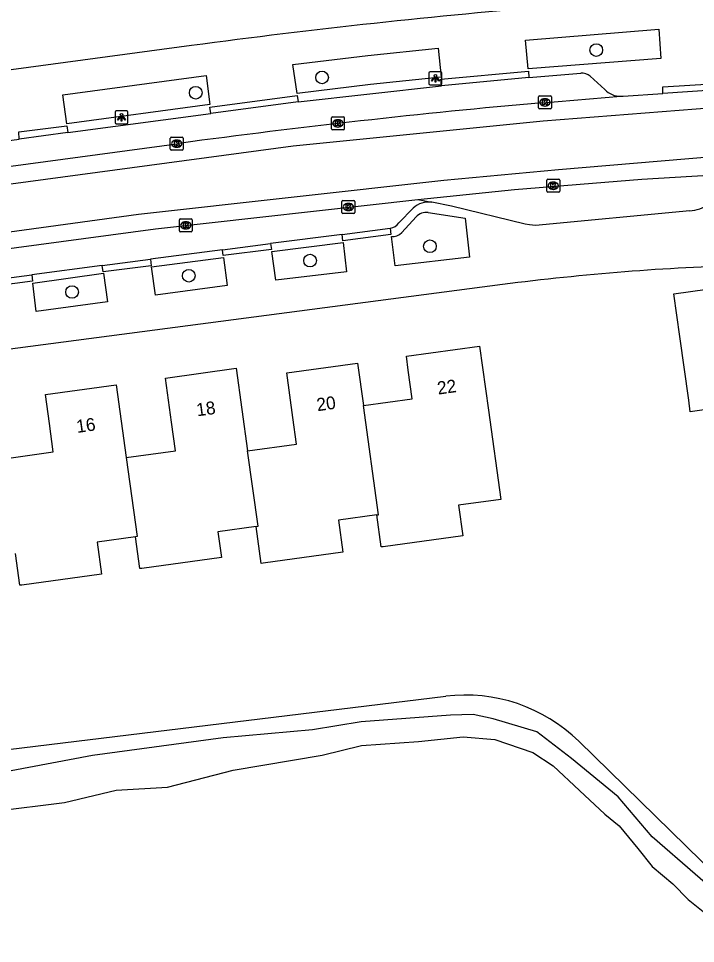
# Model space of a CAD drawing. Extents: x 163427 to 164190, y 380331 to 381641.
# Drawn here: x 163553.6 to 163606.1, y 380852.1 to 380923.8 of the extents above; entities that cross this region are included whole.
import ezdxf

# ---------------------------------------------------------------- set-up
doc = ezdxf.new("R2010")
doc.units = 0
for name, color, linetype in [('IMGEO_Boom', 7, 'Continuous'), ('IMGEO_Fietspad_gesloten', 7, 'Continuous'), ('IMGEO_Gemengd_bos', 7, 'Continuous'), ('IMGEO_Hek', 7, 'Continuous'), ('IMGEO_Kolk', 7, 'Continuous'), ('IMGEO_Lichtpunt', 7, 'Continuous'), ('IMGEO_Pand', 7, 'Continuous'), ('IMGEO_Pand_nummerreeks', 7, 'Continuous'), ('IMGEO_Rijbaan_lokaal_gesloten', 7, 'Continuous'), ('IMGEO_Rijbaan_lokaal_open', 7, 'Continuous'), ('IMGEO_Voetpad_open', 7, 'Continuous'), ('IMGEO_Waterloop', 7, 'Continuous')]:
    doc.layers.add(name, color=color, linetype=linetype)

msp = doc.modelspace()

# ---------------------------------------------------------------- linework, layer by layer
at = {"layer": 'IMGEO_Boom'}
for centre in [(163598.403, 380921.383), (163577.143, 380919.26), (163567.348, 380918.08), (163585.502, 380906.177), (163576.207, 380905.06), (163566.806, 380903.885), (163557.758, 380902.627)]:
    msp.add_circle(centre, 0.489, dxfattribs=at)
at = {"layer": 'IMGEO_Fietspad_gesloten'}
msp.add_lwpolyline([(163546.112, 380905.102), (163564.218, 380907.521), (163584.562, 380909.802)], dxfattribs=at)
at = {"layer": 'IMGEO_Gemengd_bos'}
for points in [[(163493.384, 380859.911), (163586.726, 380871.286)], [(163597.048, 380867.792), (163612.499, 380852.69), (163645.162, 380821.2)]]:
    msp.add_lwpolyline(points, dxfattribs=at)
msp.add_arc((163588.249, 380858.793), 12.586, 45.64563, 96.95242, dxfattribs=at)
at = {"layer": 'IMGEO_Hek'}
msp.add_lwpolyline([(163645.162, 380821.2), (163612.499, 380852.69), (163597.048, 380867.792)], dxfattribs=at)
at = {"layer": 'IMGEO_Kolk'}
for p, q in [((163593.922, 380916.901), (163593.922, 380917.753)), ((163593.997, 380917.827), (163594.849, 380917.827)), ((163594.41, 380917.607), (163594.435, 380917.607)), ((163594.923, 380917.753), (163594.923, 380916.901)), ((163594.433, 380917.047), (163594.408, 380917.047)), ((163577.941, 380916.199), (163578.793, 380916.199)), ((163594.849, 380916.827), (163593.997, 380916.827)), ((163577.866, 380915.273), (163577.866, 380916.125)), ((163578.354, 380915.979), (163578.379, 380915.979)), ((163578.867, 380916.125), (163578.867, 380915.273)), ((163578.793, 380915.199), (163577.941, 380915.199)), ((163578.377, 380915.419), (163578.352, 380915.419)), ((163565.374, 380913.706), (163565.374, 380914.558)), ((163565.449, 380914.632), (163566.301, 380914.632)), ((163565.862, 380914.412), (163565.887, 380914.412)), ((163566.375, 380914.558), (163566.375, 380913.706)), ((163566.301, 380913.632), (163565.449, 380913.632)), ((163565.885, 380913.852), (163565.86, 380913.852)), ((163594.569, 380910.437), (163594.569, 380911.289)), ((163594.644, 380911.363), (163595.496, 380911.363)), ((163595.057, 380911.143), (163595.082, 380911.143)), ((163595.57, 380911.289), (163595.57, 380910.437)), ((163595.08, 380910.583), (163595.055, 380910.583)), ((163578.755, 380909.717), (163579.607, 380909.717)), ((163595.496, 380910.363), (163594.644, 380910.363)), ((163578.68, 380908.791), (163578.68, 380909.643)), ((163579.168, 380909.497), (163579.193, 380909.497)), ((163579.681, 380909.643), (163579.681, 380908.791)), ((163566.15, 380908.298), (163567.002, 380908.298)), ((163579.607, 380908.717), (163578.755, 380908.717)), ((163579.191, 380908.937), (163579.166, 380908.937)), ((163566.075, 380907.372), (163566.075, 380908.224)), ((163566.563, 380908.078), (163566.588, 380908.078)), ((163567.076, 380908.224), (163567.076, 380907.372)), ((163567.002, 380907.298), (163566.15, 380907.298)), ((163566.586, 380907.518), (163566.561, 380907.518))]:
    msp.add_line(p, q, dxfattribs=at)
for points in [[(163593.922, 380916.901), (163593.922, 380917.753)], [(163593.997, 380917.827), (163594.849, 380917.827)], [(163594.923, 380917.753), (163594.923, 380916.901)], [(163594.243, 380917.527), (163594.366, 380917.527), (163594.366, 380917.376), (163594.496, 380917.527), (163594.66, 380917.527), (163594.514, 380917.376), (163594.667, 380917.127), (163594.515, 380917.127), (163594.43, 380917.291), (163594.366, 380917.224), (163594.366, 380917.127), (163594.243, 380917.127), (163594.243, 380917.527)], [(163577.941, 380916.199), (163578.793, 380916.199)], [(163594.849, 380916.827), (163593.997, 380916.827)], [(163577.866, 380915.273), (163577.866, 380916.125)], [(163578.187, 380915.899), (163578.31, 380915.899), (163578.31, 380915.748), (163578.44, 380915.899), (163578.604, 380915.899), (163578.458, 380915.748), (163578.611, 380915.499), (163578.459, 380915.499), (163578.374, 380915.663), (163578.31, 380915.596), (163578.31, 380915.499), (163578.187, 380915.499), (163578.187, 380915.899)], [(163578.867, 380916.125), (163578.867, 380915.273)], [(163578.793, 380915.199), (163577.941, 380915.199)], [(163565.374, 380913.706), (163565.374, 380914.558)], [(163565.449, 380914.632), (163566.301, 380914.632)], [(163565.695, 380914.332), (163565.818, 380914.332), (163565.818, 380914.181), (163565.948, 380914.332), (163566.112, 380914.332), (163565.966, 380914.181), (163566.119, 380913.932), (163565.967, 380913.932), (163565.882, 380914.096), (163565.818, 380914.029), (163565.818, 380913.932), (163565.695, 380913.932), (163565.695, 380914.332)], [(163566.375, 380914.558), (163566.375, 380913.706)], [(163566.301, 380913.632), (163565.449, 380913.632)], [(163594.569, 380910.437), (163594.569, 380911.289)], [(163594.644, 380911.363), (163595.496, 380911.363)], [(163595.57, 380911.289), (163595.57, 380910.437)], [(163594.89, 380911.063), (163595.013, 380911.063), (163595.013, 380910.912), (163595.143, 380911.063), (163595.307, 380911.063), (163595.161, 380910.912), (163595.314, 380910.663), (163595.162, 380910.663), (163595.077, 380910.827), (163595.013, 380910.76), (163595.013, 380910.663), (163594.89, 380910.663), (163594.89, 380911.063)], [(163578.755, 380909.717), (163579.607, 380909.717)], [(163595.496, 380910.363), (163594.644, 380910.363)], [(163578.68, 380908.791), (163578.68, 380909.643)], [(163579.001, 380909.417), (163579.124, 380909.417), (163579.124, 380909.266), (163579.254, 380909.417), (163579.418, 380909.417), (163579.272, 380909.266), (163579.425, 380909.017), (163579.273, 380909.017), (163579.188, 380909.181), (163579.124, 380909.114), (163579.124, 380909.017), (163579.001, 380909.017), (163579.001, 380909.417)], [(163579.681, 380909.643), (163579.681, 380908.791)], [(163566.15, 380908.298), (163567.002, 380908.298)], [(163579.607, 380908.717), (163578.755, 380908.717)], [(163566.075, 380907.372), (163566.075, 380908.224)], [(163566.396, 380907.998), (163566.519, 380907.998), (163566.519, 380907.847), (163566.649, 380907.998), (163566.813, 380907.998), (163566.667, 380907.847), (163566.82, 380907.598), (163566.668, 380907.598), (163566.583, 380907.762), (163566.519, 380907.695), (163566.519, 380907.598), (163566.396, 380907.598), (163566.396, 380907.998)], [(163567.076, 380908.224), (163567.076, 380907.372)], [(163567.002, 380907.298), (163566.15, 380907.298)]]:
    msp.add_lwpolyline(points, dxfattribs=at)
for centre, start, end in [((163593.999, 380917.751), 91.55205, 178.44795), ((163593.999, 380917.751), 91.55205, 178.44795), ((163594.847, 380917.751), 1.55205, 88.44795), ((163594.847, 380917.751), 1.55205, 88.44795), ((163593.999, 380916.903), 181.55205, 268.44795), ((163593.999, 380916.903), 181.55205, 268.44795), ((163594.847, 380916.903), 271.55205, 358.44795), ((163594.847, 380916.903), 271.55205, 358.44795), ((163577.943, 380916.123), 91.55205, 178.44795), ((163577.943, 380916.123), 91.55205, 178.44795), ((163578.791, 380916.123), 1.55205, 88.44795), ((163578.791, 380916.123), 1.55205, 88.44795), ((163577.943, 380915.275), 181.55205, 268.44795), ((163577.943, 380915.275), 181.55205, 268.44795), ((163578.791, 380915.275), 271.55205, 358.44795), ((163578.791, 380915.275), 271.55205, 358.44795), ((163565.451, 380914.556), 91.55205, 178.44795), ((163565.451, 380914.556), 91.55205, 178.44795), ((163566.299, 380914.556), 1.55205, 88.44795), ((163566.299, 380914.556), 1.55205, 88.44795), ((163565.451, 380913.708), 181.55205, 268.44795), ((163565.451, 380913.708), 181.55205, 268.44795), ((163566.299, 380913.708), 271.55205, 358.44795), ((163566.299, 380913.708), 271.55205, 358.44795), ((163594.646, 380911.287), 91.55205, 178.44795), ((163594.646, 380911.287), 91.55205, 178.44795), ((163595.494, 380911.287), 1.55205, 88.44795), ((163595.494, 380911.287), 1.55205, 88.44795), ((163594.646, 380910.439), 181.55205, 268.44795), ((163594.646, 380910.439), 181.55205, 268.44795), ((163595.494, 380910.439), 271.55205, 358.44795), ((163595.494, 380910.439), 271.55205, 358.44795), ((163578.757, 380909.641), 91.55205, 178.44795), ((163578.757, 380909.641), 91.55205, 178.44795), ((163579.605, 380909.641), 1.55205, 88.44795), ((163579.605, 380909.641), 1.55205, 88.44795), ((163566.152, 380908.222), 91.55205, 178.44795), ((163566.152, 380908.222), 91.55205, 178.44795), ((163567, 380908.222), 1.55205, 88.44795), ((163567, 380908.222), 1.55205, 88.44795), ((163578.757, 380908.793), 181.55205, 268.44795), ((163578.757, 380908.793), 181.55205, 268.44795), ((163579.605, 380908.793), 271.55205, 358.44795), ((163579.605, 380908.793), 271.55205, 358.44795), ((163566.152, 380907.374), 181.55205, 268.44795), ((163566.152, 380907.374), 181.55205, 268.44795), ((163567, 380907.374), 271.55205, 358.44795), ((163567, 380907.374), 271.55205, 358.44795)]:
    msp.add_arc(centre, 0.0765, start, end, dxfattribs=at)
for centre, major_axis, ratio, start_param, end_param in [((163594.409, 380917.327), (-0.387, 0.002), 0.722429, 4.712389, 7.853982), ((163594.434, 380917.327), (-0.39, 0.002), 0.717154, 1.570796, 4.712389), ((163578.353, 380915.699), (-0.387, 0.002), 0.722429, 4.712389, 7.853982), ((163578.378, 380915.699), (-0.39, 0.002), 0.717154, 1.570796, 4.712389), ((163565.861, 380914.132), (-0.387, 0.002), 0.722429, 4.712389, 7.853982), ((163565.886, 380914.132), (-0.39, 0.002), 0.717154, 1.570796, 4.712389), ((163595.056, 380910.863), (-0.387, 0.002), 0.722429, 4.712389, 7.853982), ((163595.081, 380910.863), (-0.39, 0.002), 0.717154, 1.570796, 4.712389), ((163579.167, 380909.217), (-0.387, 0.002), 0.722429, 4.712389, 7.853982), ((163579.192, 380909.217), (-0.39, 0.002), 0.717154, 1.570796, 4.712389), ((163566.562, 380907.798), (-0.387, 0.002), 0.722429, 4.712389, 7.853982), ((163566.587, 380907.798), (-0.39, 0.002), 0.717154, 1.570796, 4.712389)]:
    msp.add_ellipse(centre, major_axis=major_axis, ratio=ratio, start_param=start_param, end_param=end_param, dxfattribs=at)
at = {"layer": 'IMGEO_Lichtpunt'}
for p, q in [((163585.431, 380919.593), (163585.431, 380918.786)), ((163585.431, 380919.593), (163585.431, 380918.786)), ((163586.333, 380919.688), (163585.525, 380919.688)), ((163586.333, 380919.688), (163585.525, 380919.688)), ((163586.427, 380918.786), (163586.427, 380919.593)), ((163586.427, 380918.786), (163586.427, 380919.593)), ((163585.525, 380918.692), (163586.333, 380918.692)), ((163585.525, 380918.692), (163586.333, 380918.692)), ((163561.088, 380916.573), (163561.088, 380915.766)), ((163561.088, 380916.573), (163561.088, 380915.766)), ((163561.99, 380916.668), (163561.182, 380916.668)), ((163561.99, 380916.668), (163561.182, 380916.668)), ((163562.084, 380915.766), (163562.084, 380916.573)), ((163562.084, 380915.766), (163562.084, 380916.573)), ((163561.182, 380915.672), (163561.99, 380915.672)), ((163561.182, 380915.672), (163561.99, 380915.672))]:
    msp.add_line(p, q, dxfattribs=at)
for points in [[(163585.805, 380919.257), (163585.844, 380919.229), (163585.656, 380918.967), (163585.618, 380918.994), (163585.805, 380919.257)], [(163585.907, 380919.209), (163585.954, 380919.209), (163585.954, 380918.887), (163585.907, 380918.887), (163585.907, 380919.209)], [(163586.017, 380919.229), (163586.055, 380919.256), (163586.242, 380918.994), (163586.203, 380918.966), (163586.017, 380919.229)], [(163561.462, 380916.237), (163561.501, 380916.209), (163561.313, 380915.947), (163561.275, 380915.974), (163561.462, 380916.237)], [(163561.564, 380916.189), (163561.611, 380916.189), (163561.611, 380915.867), (163561.564, 380915.867), (163561.564, 380916.189)], [(163561.674, 380916.209), (163561.712, 380916.236), (163561.899, 380915.974), (163561.86, 380915.946), (163561.674, 380916.209)]]:
    msp.add_lwpolyline(points, dxfattribs=at)
for centre in [(163585.93, 380919.391), (163561.587, 380916.371)]:
    msp.add_circle(centre, 0.0994, dxfattribs=at)
for centre, start, end in [((163585.525, 380919.593), 90, 180), ((163585.525, 380919.593), 90, 180), ((163586.333, 380919.593), 0, 90), ((163586.333, 380919.593), 0, 90), ((163585.525, 380918.786), 180, 270), ((163585.525, 380918.786), 180, 270), ((163586.333, 380918.786), 270, 0), ((163586.333, 380918.786), 270, 360), ((163561.182, 380916.573), 90, 180), ((163561.182, 380916.573), 90, 180), ((163561.99, 380916.573), 0, 90), ((163561.99, 380916.573), 0, 90), ((163561.182, 380915.766), 180, 270), ((163561.182, 380915.766), 180, 270), ((163561.99, 380915.766), 270, 0), ((163561.99, 380915.766), 270, 360)]:
    msp.add_arc(centre, 0.0946, start, end, dxfattribs=at)
at = {"layer": 'IMGEO_Pand'}
for points in [[(163609.011, 380884.11), (163607.679, 380893.619), (163605.698, 380893.341), (163605.573, 380894.234), (163604.88, 380899.185), (163604.416, 380902.498), (163612.354, 380903.601), (163612.81, 380900.292), (163613.286, 380896.835), (163616.257, 380897.248), (163617.925, 380885.358), (163612.974, 380884.665), (163609.011, 380884.11)], [(163580.354, 380893.822), (163584.135, 380894.343), (163583.829, 380896.562), (163583.68, 380897.642), (163589.343, 380898.423), (163590.036, 380893.472), (163591.006, 380886.545), (163587.731, 380886.094), (163588.056, 380883.729), (163581.873, 380882.879), (163581.724, 380882.858), (163581.382, 380885.341)], [(163571.367, 380890.303), (163575.165, 380890.826), (163574.88, 380892.897), (163574.403, 380896.364), (163579.896, 380897.121), (163580.354, 380893.822)], [(163561.962, 380889.797), (163565.776, 380890.324), (163565.471, 380892.532), (163564.998, 380895.956), (163570.479, 380896.712), (163571.367, 380890.303)], [(163552.496, 380889.7), (163556.301, 380890.225), (163555.997, 380892.424), (163555.687, 380894.67), (163561.178, 380895.428), (163561.962, 380889.797)], [(163581.382, 380885.341), (163581.528, 380885.361), (163580.354, 380893.822)], [(163561.962, 380889.797), (163562.815, 380883.673), (163562.67, 380883.653)], [(163572.028, 380884.447), (163572.175, 380884.467), (163571.367, 380890.303)], [(163581.382, 380885.341), (163578.413, 380884.933), (163578.755, 380882.449), (163572.572, 380881.598), (163572.423, 380881.577), (163572.028, 380884.447)], [(163572.028, 380884.447), (163569.059, 380884.038), (163569.333, 380882.049), (163563.159, 380881.2), (163563.01, 380881.179), (163562.67, 380883.653)], [(163562.67, 380883.653), (163559.701, 380883.244), (163560.043, 380880.76), (163553.85, 380879.908), (163553.701, 380879.887), (163553.362, 380882.351)]]:
    msp.add_lwpolyline(points, dxfattribs=at)
at = {"layer": 'IMGEO_Rijbaan_lokaal_gesloten'}
for points in [[(163607.38, 380918.278), (163607.459, 380916.901), (163594.29, 380915.88), (163574.895, 380913.939), (163529.367, 380907.811), (163518.508, 380906.15), (163518.238, 380907.701)], [(163594.236, 380917.3), (163600.308, 380917.8)], [(163600.308, 380917.8), (163600.49, 380917.815), (163603.576, 380918.027)], [(163607.38, 380918.278), (163603.576, 380918.027)], [(163682.084, 380914.454), (163682.039, 380914.453), (163667.849, 380914.247), (163641.715, 380914.042), (163613.539, 380913.634), (163595.47, 380912.102), (163586.588, 380911.285), (163562.905, 380908.63), (163550.246, 380906.894), (163542.996, 380905.847), (163538.913, 380905.03), (163527.53, 380902.17), (163513.545, 380898.902), (163493.877, 380894.347)], [(163518.238, 380907.701), (163566.057, 380914.153)]]:
    msp.add_lwpolyline(points, dxfattribs=at)
msp.add_arc((163647.924, 380308.83), 610.834, 95.042405, 97.702246, dxfattribs=at)
at = {"layer": 'IMGEO_Rijbaan_lokaal_open'}
for points in [[(163593.185, 380919.252), (163586.408, 380918.617)], [(163593.185, 380919.252), (163597.205, 380919.598)], [(163597.924, 380919.35), (163599.078, 380918.328)], [(163575.285, 380917.378), (163586.408, 380918.617)], [(163575.285, 380917.378), (163568.512, 380916.471)], [(163557.432, 380914.987), (163568.512, 380916.471)], [(163557.432, 380914.987), (163553.66, 380914.482)], [(163521.671, 380910.197), (163553.66, 380914.482)], [(163584.562, 380909.802), (163592.055, 380910.574), (163601.938, 380911.38), (163611.837, 380911.964)], [(163584.562, 380909.802), (163585.658, 380909.583)], [(163605.654, 380908.909), (163593.683, 380907.793), (163593.225, 380907.828), (163592.888, 380907.877), (163587.172, 380909.281), (163585.658, 380909.583)]]:
    msp.add_lwpolyline(points, dxfattribs=at)
for centre, radius, start, end in [((163597.259, 380918.587), 1.012, 48.89889, 93.04008), ((163600.269, 380919.406), 1.607, 222.15316, 271.38221), ((163604.989, 380913.587), 4.725, 278.08572, 297.23979)]:
    msp.add_arc(centre, radius, start, end, dxfattribs=at)
at = {"layer": 'IMGEO_Voetpad_open'}
for points in [[(163592.914, 380922.155), (163603.244, 380923.005), (163603.418, 380920.741), (163593.119, 380919.928), (163592.914, 380922.155)], [(163567.021, 380921.728), (163552.058, 380919.715)], [(163580.908, 380918.708), (163575.202, 380918.02), (163574.873, 380920.263), (163580.701, 380920.965), (163586.145, 380921.539), (163586.369, 380919.291), (163580.908, 380918.708)], [(163586.408, 380918.617), (163586.361, 380919.121), (163593.139, 380919.749), (163593.185, 380919.252)], [(163568.45, 380917.161), (163557.361, 380915.675), (163557.034, 380917.924), (163568.153, 380919.422), (163568.45, 380917.161)], [(163603.576, 380918.027), (163603.576, 380918.542), (163607.345, 380918.78), (163607.38, 380918.278)], [(163568.512, 380916.471), (163568.446, 380916.966), (163575.219, 380917.873), (163575.285, 380917.378)], [(163553.66, 380914.482), (163553.616, 380915.034), (163557.361, 380915.523), (163557.432, 380914.987)], [(163584.193, 380909.131), (163583.103, 380907.978)], [(163585.357, 380908.782), (163588.24, 380908.352), (163588.583, 380905.341), (163582.816, 380904.651)], [(163583.32, 380907.233), (163584.437, 380908.45)], [(163582.425, 380907.582), (163582.474, 380907.078), (163578.756, 380906.604), (163578.687, 380907.096)], [(163578.687, 380907.096), (163582.425, 380907.582)], [(163578.687, 380907.096), (163573.153, 380906.376)], [(163582.816, 380904.651), (163582.517, 380906.924)], [(163573.153, 380906.376), (163573.222, 380905.916), (163569.48, 380905.45), (163569.42, 380905.89)], [(163569.42, 380905.89), (163573.153, 380906.376)], [(163573.544, 380903.543), (163573.243, 380905.769), (163578.776, 380906.459), (163579.043, 380904.199), (163573.544, 380903.543)], [(163569.42, 380905.89), (163563.836, 380905.164)], [(163560.097, 380904.678), (163554.627, 380903.966)], [(163563.836, 380905.164), (163563.9, 380904.669), (163560.161, 380904.183), (163560.097, 380904.678)], [(163560.097, 380904.678), (163563.836, 380905.164)], [(163564.212, 380902.374), (163563.913, 380904.583), (163569.49, 380905.3), (163569.794, 380903.122), (163564.212, 380902.374)], [(163554.627, 380903.966), (163554.691, 380903.471), (163550.936, 380902.983), (163550.872, 380903.478)], [(163550.872, 380903.478), (163554.627, 380903.966)], [(163560.496, 380901.855), (163554.967, 380901.118), (163554.708, 380903.318), (163560.181, 380904.075), (163560.496, 380901.855)], [(163591.127, 380903.206), (163517.891, 380893.601), (163517.396, 380893.496), (163516.914, 380893.369), (163500, 380888.682), (163485.003, 380884.527)]]:
    msp.add_lwpolyline(points, dxfattribs=at)
for centre, radius, start, end in [((163640.338, 380379.091), 547.567, 94.70683, 97.69477), ((163585.411, 380907.784), 1.816, 82.18329, 132.11009), ((163585.188, 380907.81), 0.987, 80.13718, 139.54876), ((163582.276, 380908.615), 1.044, 278.1897, 322.3862), ((163582.568, 380907.99), 1.067, 267.27843, 314.81571), ((163615.756, 380711.692), 193.091, 91.67175, 97.32814)]:
    msp.add_arc(centre, radius, start, end, dxfattribs=at)
at = {"layer": 'IMGEO_Waterloop'}
for points in [[(163609.418, 380854.587), (163602.738, 380860.396), (163600.091, 380863.489), (163596.479, 380866.45), (163593.799, 380868.531), (163590.402, 380869.544), (163588.868, 380869.866), (163587.1, 380869.822), (163580.175, 380869.293), (163576.386, 380868.687), (163569.478, 380868.07), (163559.351, 380866.7), (163553.023, 380865.515), (163545.236, 380864.606), (163540.638, 380864.003), (163522.737, 380861.53), (163508.323, 380859.904), (163503.533, 380859.052)], [(163551.74, 380862.387), (163557.177, 380863.045), (163561.172, 380863.994), (163565.142, 380864.239), (163570.24, 380865.552), (163577.161, 380866.718), (163580.202, 380867.462), (163584.611, 380867.785), (163588.087, 380868.149), (163590.525, 380867.926), (163593.486, 380866.93), (163595.056, 380865.891), (163597.094, 380863.981), (163599.061, 380862.135), (163600.17, 380861.245), (163601.616, 380859.486), (163602.744, 380858.087), (163604.347, 380856.748), (163605.519, 380855.538), (163607.079, 380854.299)]]:
    msp.add_lwpolyline(points, dxfattribs=at)

# ---------------------------------------------------------------- texts
at = {"layer": 'IMGEO_Pand_nummerreeks'}
for s, rotation, p in [('22', 7.84952, (163586.138, 380894.67)), ('18', 7.85525, (163567.462, 380892.985)), ('20', 7.84952, (163576.782, 380893.381)), ('16', 7.86098, (163558.153, 380891.699))]:
    msp.add_text(s, height=1, rotation=rotation, dxfattribs=at).set_placement(p)

doc.saveas('drawing.dxf')
